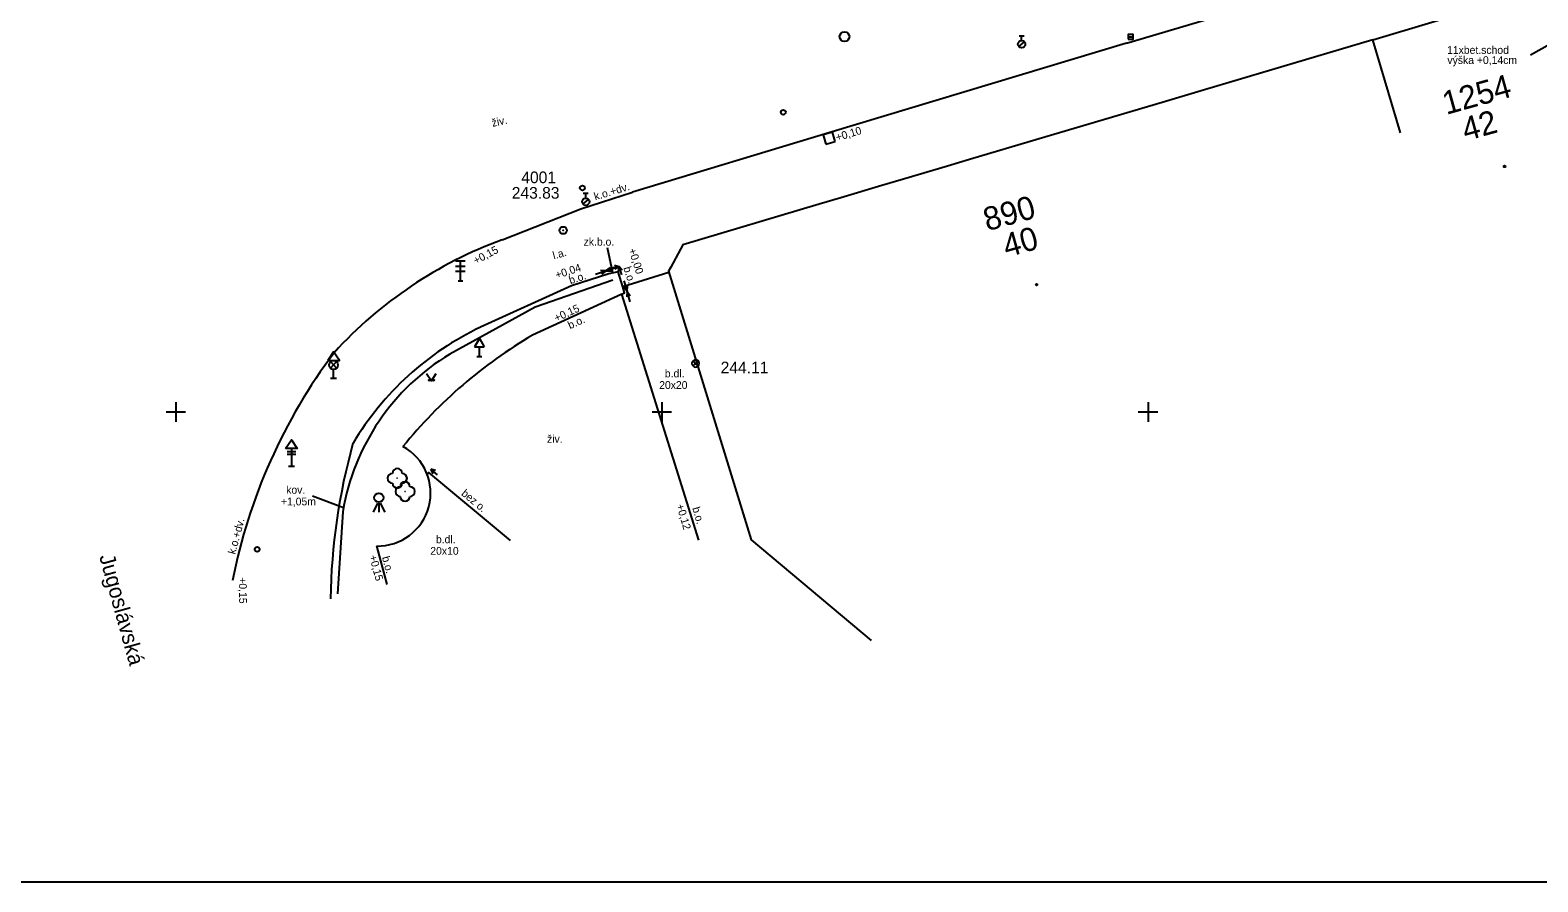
# Model space of a CAD drawing. Extents: x -597333 to -596488, y -1158921 to -1158644.
# Drawn here: x -596882.5 to -596805, y -1158799.2 to -1158755.4 of the extents above; entities that cross this region are included whole.
import ezdxf

# ---------------------------------------------------------------- set-up
doc = ezdxf.new("R2010")
doc.units = 0
for name, color, linetype in [('Vrstva 1', 7, 'Continuous'), ('Vrstva 14', 7, 'Continuous'), ('Vrstva 15', 7, 'Continuous'), ('Vrstva 19', 7, 'Continuous'), ('Vrstva 2', 7, 'Continuous'), ('Vrstva 22', 7, 'Continuous'), ('Vrstva 23', 7, 'Continuous'), ('Vrstva 24', 7, 'Continuous'), ('Vrstva 25', 7, 'Continuous'), ('Vrstva 26', 7, 'Continuous'), ('Vrstva 4', 7, 'Continuous'), ('Vrstva 42', 7, 'Continuous'), ('Vrstva 43', 7, 'Continuous'), ('Vrstva 44', 7, 'Continuous'), ('Vrstva 49', 7, 'Continuous'), ('Vrstva 5', 7, 'Continuous'), ('Vrstva 50', 7, 'Continuous'), ('Vrstva 62', 7, 'Continuous'), ('Vrstva 7', 7, 'Continuous')]:
    doc.layers.add(name, color=color, linetype=linetype)

msp = doc.modelspace()

# ---------------------------------------------------------------- linework, layer by layer
at = {"layer": 'Vrstva 1'}
msp.add_lwpolyline([(-596908.148, -1158651.282), (-596908.148, -1158799.157), (-596698.148, -1158799.157), (-596698.148, -1158650.657), (-596905.25, -1158650.657)], dxfattribs=at)
at = {"layer": 'Vrstva 14'}
msp.add_lwpolyline([(-596862.104, -1158773.017), (-596861.854, -1158773.392), (-596861.604, -1158773.017)], dxfattribs=at)
for centre, radius in [((-596861.979, -1158773.367), 0.025), ((-596861.729, -1158773.367), 0.025), ((-596863.61, -1158778.41), 0.00025), ((-596863.21, -1158779.09), 0.00025)]:
    msp.add_circle(centre, radius, dxfattribs=at)
for centre, start, end in [((-596863.86, -1158778.41), 89.99999, 269.99999), ((-596863.61, -1158778.16), 0, 179.99999), ((-596863.36, -1158778.41), 270, 89.99999), ((-596863.61, -1158778.66), 179.99999, 359.99999), ((-596863.46, -1158779.09), 89.99999, 269.99999), ((-596863.21, -1158778.84), 0, 179.99999), ((-596862.96, -1158779.09), 270, 89.99999), ((-596863.21, -1158779.34), 179.99999, 359.99999)]:
    msp.add_arc(centre, 0.25, start, end, dxfattribs=at)
at = {"layer": 'Vrstva 15'}
for centre in [(-596806.663, -1158762.374), (-596830.73, -1158768.456)]:
    msp.add_circle(centre, 0.0438, dxfattribs=at)
at = {"layer": 'Vrstva 19'}
for p, q in [((-596860.113, -1158767.251), (-596860.613, -1158767.251)), ((-596860.363, -1158768.251), (-596860.363, -1158767.251)), ((-596860.613, -1158767.501), (-596860.113, -1158767.501)), ((-596860.613, -1158767.751), (-596860.113, -1158767.751)), ((-596860.488, -1158768.251), (-596860.238, -1158768.251)), ((-596859.39, -1158771.217), (-596859.64, -1158771.65)), ((-596859.39, -1158771.217), (-596859.14, -1158771.65)), ((-596859.64, -1158771.65), (-596859.14, -1158771.65)), ((-596859.39, -1158772.15), (-596859.39, -1158771.65)), ((-596859.515, -1158772.15), (-596859.265, -1158772.15))]:
    msp.add_line(p, q, dxfattribs=at)
at = {"layer": 'Vrstva 2'}
for p, q in [((-596848.402, -1158772.368), (-596848.27, -1158772.5)), ((-596848.402, -1158772.632), (-596848.27, -1158772.5)), ((-596848.27, -1158772.5), (-596848.402, -1158772.632)), ((-596848.138, -1158772.368), (-596848.27, -1158772.5)), ((-596848.138, -1158772.632), (-596848.27, -1158772.5)), ((-596848.27, -1158772.5), (-596848.138, -1158772.632)), ((-596848.27, -1158772.5), (-596848.138, -1158772.632))]:
    msp.add_line(p, q, dxfattribs=at)
for radius in [0.188, 0.00025]:
    msp.add_circle((-596855.08, -1158765.66), radius, dxfattribs=at)
for start, end in [(134.99216, 225.00785), (44.99215, 135.00784), (224.99216, 315.00785), (314.99214, 45.00783)]:
    msp.add_arc((-596848.27, -1158772.5), 0.187, start, end, dxfattribs=at)
at = {"layer": 'Vrstva 22'}
for points in [[(-596852.52, -1158768.22), (-596856.52, -1158769.61), (-596860.91, -1158772.02)], [(-596866.42, -1158780.13), (-596866.69, -1158784.35)]]:
    msp.add_lwpolyline(points, dxfattribs=at)
msp.add_arc((-596854.834, -1158782.075), 11.748, 121.14344, 170.47155, dxfattribs=at)
at = {"layer": 'Vrstva 23'}
for p, q in [((-596841.222, -1158760.617), (-596841.702, -1158760.757)), ((-596841.702, -1158760.757), (-596841.563, -1158761.237)), ((-596841.563, -1158761.237), (-596841.083, -1158761.097)), ((-596841.083, -1158761.097), (-596841.222, -1158760.617))]:
    msp.add_line(p, q, dxfattribs=at)
at = {"layer": 'Vrstva 24'}
for p, q in [((-596831.625, -1158755.653), (-596831.375, -1158755.653)), ((-596831.5, -1158755.903), (-596831.5, -1158755.653)), ((-596831.647, -1158756.205), (-596831.352, -1158755.974)), ((-596854.067, -1158764.306), (-596853.772, -1158764.074)), ((-596854.045, -1158763.752), (-596853.795, -1158763.752)), ((-596853.92, -1158764.002), (-596853.92, -1158763.752))]:
    msp.add_line(p, q, dxfattribs=at)
for centre, radius in [((-596831.5, -1158756.09), 0.188), ((-596843.76, -1158759.59), 0.125), ((-596854.09, -1158763.48), 0.125), ((-596853.92, -1158764.19), 0.188)]:
    msp.add_circle(centre, radius, dxfattribs=at)
at = {"layer": 'Vrstva 25'}
msp.add_line((-596826.015, -1158755.71), (-596825.765, -1158755.71), dxfattribs=at)
msp.add_lwpolyline([(-596826.015, -1158755.836), (-596825.765, -1158755.836), (-596825.765, -1158755.585), (-596826.015, -1158755.585)], close=True, dxfattribs=at)
msp.add_circle((-596840.61, -1158755.7), 0.25, dxfattribs=at)
at = {"layer": 'Vrstva 26'}
msp.add_circle((-596870.82, -1158782.06), 0.125, dxfattribs=at)
at = {"layer": 'Vrstva 4'}
msp.add_line((-596812.007, -1158760.653), (-596813.43, -1158755.86), dxfattribs=at)
for points in [[(-596813.43, -1158755.86), (-596804.67, -1158753.22), (-596803.247, -1158757.941)], [(-596813.43, -1158755.86), (-596822.092, -1158758.432)], [(-596824.27, -1158759.079), (-596829.551, -1158760.646)], [(-596830.604, -1158760.959), (-596834.184, -1158762.022)], [(-596835.306, -1158762.355), (-596837.574, -1158763.029)], [(-596838.685, -1158763.358), (-596840.805, -1158763.988)], [(-596841.908, -1158764.315), (-596848.93, -1158766.4), (-596849.048, -1158766.62)], [(-596849.546, -1158767.547), (-596849.66, -1158767.76), (-596845.41, -1158781.58), (-596839.246, -1158786.755)]]:
    msp.add_lwpolyline(points, dxfattribs=at)
at = {"layer": 'Vrstva 44'}
for p, q in [((-596866.74, -1158772.41), (-596867.04, -1158772.754)), ((-596867.04, -1158772.41), (-596866.74, -1158772.754)), ((-596866.89, -1158773.26), (-596866.89, -1158772.81)), ((-596867.04, -1158773.26), (-596866.74, -1158773.26)), ((-596869.275, -1158777.027), (-596868.827, -1158777.027)), ((-596869.275, -1158777.177), (-596868.832, -1158777.177)), ((-596869.055, -1158776.877), (-596869.055, -1158777.777)), ((-596869.205, -1158777.777), (-596868.905, -1158777.777)), ((-596864.634, -1158779.693), (-596864.86, -1158780.145)), ((-596864.56, -1158779.695), (-596864.56, -1158780.145)), ((-596864.485, -1158779.693), (-596864.26, -1158780.145))]:
    msp.add_line(p, q, dxfattribs=at)
msp.add_lwpolyline([(-596867.19, -1158772.354), (-596866.59, -1158772.354), (-596866.89, -1158771.904), (-596867.19, -1158772.354)], dxfattribs=at)
msp.add_lwpolyline([(-596869.355, -1158776.882), (-596869.055, -1158776.427), (-596868.755, -1158776.882)], close=True, dxfattribs=at)
for centre, radius in [((-596866.89, -1158772.582), 0.228), ((-596864.56, -1158779.4), 0.234)]:
    msp.add_circle(centre, radius, dxfattribs=at)
at = {"layer": 'Vrstva 49'}
for p, q in [((-596805.322, -1158756.634), (-596803.453, -1158755.599)), ((-596853.421, -1158767.907), (-596852.88, -1158767.747)), ((-596852.88, -1158767.748), (-596853.163, -1158767.733)), ((-596852.877, -1158767.745), (-596853.103, -1158767.914)), ((-596852.88, -1158767.748), (-596852.654, -1158767.579)), ((-596852.34, -1158767.588), (-596852.88, -1158767.748)), ((-596852.88, -1158767.748), (-596852.598, -1158767.763)), ((-596852.434, -1158767.453), (-596852.195, -1158767.526)), ((-596852.405, -1158767.662), (-596852.195, -1158767.526)), ((-596852.231, -1158767.773), (-596852.195, -1158767.526)), ((-596852.029, -1158767.712), (-596852.195, -1158767.526)), ((-596851.792, -1158768.805), (-596851.961, -1158768.579)), ((-596851.954, -1158768.261), (-596851.794, -1158768.802)), ((-596851.795, -1158768.802), (-596851.81, -1158769.084)), ((-596851.795, -1158768.802), (-596851.78, -1158768.519)), ((-596851.635, -1158769.342), (-596851.795, -1158768.802)), ((-596851.795, -1158768.802), (-596851.627, -1158769.027)), ((-596861.639, -1158778.011), (-596861.881, -1158777.948)), ((-596861.773, -1158778.174), (-596861.881, -1158777.948))]:
    msp.add_line(p, q, dxfattribs=at)
for points in [[(-596852.534, -1158767.844), (-596852.795, -1158766.561)], [(-596852.625, -1158767.587), (-596852.195, -1158767.526)], [(-596852.071, -1158767.942), (-596852.195, -1158767.526)], [(-596861.546, -1158778.224), (-596861.881, -1158777.948)], [(-596866.374, -1158779.92), (-596867.976, -1158779.332)]]:
    msp.add_lwpolyline(points, dxfattribs=at)
at = {"layer": 'Vrstva 5'}
for p, q in [((-596822.092, -1158758.432), (-596824.27, -1158759.079)), ((-596829.551, -1158760.646), (-596830.604, -1158760.959)), ((-596834.184, -1158762.022), (-596835.306, -1158762.355)), ((-596837.574, -1158763.029), (-596838.685, -1158763.358)), ((-596840.805, -1158763.988), (-596841.908, -1158764.315)), ((-596849.048, -1158766.62), (-596849.546, -1158767.547))]:
    msp.add_line(p, q, dxfattribs=at)
at = {"layer": 'Vrstva 62'}
for p, q in [((-596875.5, -1158775), (-596874.5, -1158775)), ((-596875, -1158774.5), (-596875, -1158775.5)), ((-596850.5, -1158775), (-596849.5, -1158775)), ((-596850, -1158774.5), (-596850, -1158775.5)), ((-596825.5, -1158775), (-596824.5, -1158775)), ((-596825, -1158774.5), (-596825, -1158775.5))]:
    msp.add_line(p, q, dxfattribs=at)
at = {"layer": 'Vrstva 7'}
msp.add_line((-596849.65, -1158767.83), (-596852.01, -1158768.57), dxfattribs=at)
for points in [[(-596826.11, -1158756.04), (-596804.37, -1158749.6), (-596804.32, -1158749.76), (-596801.86, -1158749.01), (-596801.89, -1158748.85), (-596801.12, -1158748.62), (-596800.19, -1158748.36), (-596796.83, -1158747.34)], [(-596826.11, -1158756.04), (-596841.42, -1158760.64), (-596851.52, -1158763.7)], [(-596858.22, -1158766.15), (-596854.18, -1158764.56), (-596851.52, -1158763.7)], [(-596852.06, -1158768.95), (-596851.92, -1158768.88), (-596852.01, -1158768.57), (-596852.26, -1158767.79), (-596852.74, -1158767.89), (-596854.66, -1158768.52), (-596859.33, -1158770.64)], [(-596848.11, -1158781.59), (-596852.06, -1158768.95), (-596856.66, -1158771.05)], [(-596862.08, -1158778.198), (-596862, -1158778.11), (-596857.81, -1158781.6)], [(-596864.68, -1158781.89), (-596864.15, -1158783.87)]]:
    msp.add_lwpolyline(points, dxfattribs=at)
for centre, radius, start, end in [((-596850.741, -1158786.627), 21.8, 110.06523, 137.6814), ((-596852.756, -1158784.452), 15.297, 115.4508, 149.15741), ((-596844.202, -1158792.265), 24.602, 120.4219, 140.9929), ((-596843.843, -1158789.248), 28.792, 143.07355, 168.82922), ((-596835.466, -1158785.106), 31.588, 164.39705, 179.08181), ((-596864.622, -1158779.17), 2.721, 268.76852, 61.42448)]:
    msp.add_arc(centre, radius, start, end, dxfattribs=at)

# ---------------------------------------------------------------- texts
at = {"layer": 'Vrstva 2'}
msp.add_text('4001', height=0.6, rotation=360, dxfattribs=at).set_placement((-596857.233, -1158763.235))
for s, p in [('243.83', (-596857.723, -1158764.032)), ('244.11', (-596846.981, -1158773.014))]:
    msp.add_text(s, height=0.6, dxfattribs=at).set_placement(p)
at = {"layer": 'Vrstva 42'}
msp.add_text('Jugoslávská', height=0.8, rotation=285.53185, dxfattribs=at).set_placement((-596878.949, -1158782.424))
at = {"layer": 'Vrstva 43'}
for s, p in [('1254', (-596809.664, -1158759.727)), ('42', (-596808.661, -1158761.079)), ('890', (-596833.274, -1158765.711)), ('40', (-596832.271, -1158767.063))]:
    msp.add_text(s, height=1.2, rotation=15.52539, dxfattribs=at).set_placement(p)
at = {"layer": 'Vrstva 49'}
for s, p in [('11xbet.schod', (-596809.62, -1158756.586)), ('zk.b.o.', (-596854.029, -1158766.446)), ('b.dl.', (-596849.853, -1158773.219)), ('20x20', (-596850.143, -1158773.813)), ('živ.', (-596855.91, -1158776.581)), ('kov.', (-596869.326, -1158779.202)), ('b.dl.', (-596861.624, -1158781.747)), ('20x10', (-596861.914, -1158782.34))]:
    msp.add_text(s, height=0.4, dxfattribs=at).set_placement(p)
for s, rotation, p in [('živ.', 12.46348, (-596858.709, -1158760.343)), ('k.o.+dv.', 16.85525, (-596853.428, -1158764.122)), ('l.a.', 16.03013, (-596855.556, -1158767.155)), ('b.o.', 18.16596, (-596854.708, -1158768.435)), ('b.o.', 287.77132, (-596851.989, -1158767.592)), ('b.o.', 24.53773, (-596854.73, -1158770.749)), ('bez o.', 320.20788, (-596860.353, -1158779.246)), ('k.o.+dv.', 75.12123, (-596871.947, -1158782.343)), ('b.o.', 286.51451, (-596848.445, -1158779.944)), ('b.o.', 284.98544, (-596864.403, -1158782.473))]:
    msp.add_text(s, height=0.4, rotation=rotation, dxfattribs=at).set_placement(p)
at = {"layer": 'Vrstva 50'}
for s, p in [('výška +0,14cm', (-596809.602, -1158757.107)), ('+1,05m', (-596869.596, -1158779.802))]:
    msp.add_text(s, height=0.4, dxfattribs=at).set_placement(p)
for s, rotation, p in [('+0,10', 16.72327, (-596840.994, -1158761.081)), ('+0,15', 27.94348, (-596859.57, -1158767.421)), ('+0,00', 287.77132, (-596851.727, -1158766.656)), ('+0,04', 18.16596, (-596855.407, -1158768.161)), ('+0,15', 24.53773, (-596855.431, -1158770.375)), ('+0,12', 286.51451, (-596849.265, -1158779.796)), ('+0,15', 284.98544, (-596865.062, -1158782.411)), ('+0,15', 270.65581, (-596871.758, -1158783.501))]:
    msp.add_text(s, height=0.4, rotation=rotation, dxfattribs=at).set_placement(p)

doc.saveas('drawing.dxf')
